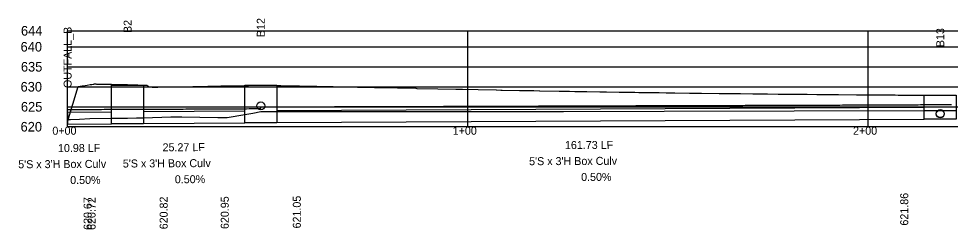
# Model space of a CAD drawing. Extents: x 2253035 to 2279930, y 13774972 to 13793443.
# Drawn here: x 2258373.2 to 2258605.9, y 13793378.5 to 13793431.3 of the extents above; entities that cross this region are included whole.
import ezdxf

# ---------------------------------------------------------------- set-up
doc = ezdxf.new("R2010")
doc.units = 0
for name, color, linetype in [('Default', 7, 'Continuous'), ('E_Utility_ATT_HH', 7, 'Continuous'), ('E_Utility_ATT_PR_PVC', 7, 'Continuous'), ('E_Utility_Electric_Overhead Electric Power Line_OE_Elevation', 7, 'Continuous'), ('E_Utility_Electric_Overhead Electric Power Line_OE_point', 7, 'Continuous'), ('E_Utillity_Water_Water Line_12in', 7, 'Continuous'), ('E_Utillity_Water_Water Line_1in', 7, 'Continuous'), ('E_Utillity_Water_Water Line_4in', 7, 'Continuous'), ('E_Utillity_Water_Water Line_8in', 7, 'Continuous')]:
    doc.layers.add(name, color=color, linetype=linetype)

msp = doc.modelspace()

# ---------------------------------------------------------------- linework, layer by layer
at = {"layer": 'Default'}
for p, q in [((2258485.4, 13793404.21), (2258485.4, 13793428.21)), ((2258585.4, 13793404.21), (2258585.4, 13793428.21))]:
    msp.add_line(p, q, dxfattribs=at)
at = {"layer": 'E_Utility_ATT_PR_PVC'}
for p, q in [((2258400.39, 13793408.64), (2258400.39, 13793408.6)), ((2258433.65, 13793409.25), (2258433.65, 13793409.17)), ((2258603.38, 13793409.85), (2258603.38, 13793409.77))]:
    msp.add_line(p, q, dxfattribs=at)
for points in [[(2258385.4, 13793408.53), (2258386.1, 13793408.54), (2258386.8, 13793408.54), (2258387.51, 13793408.54), (2258388.21, 13793408.54), (2258388.91, 13793408.55), (2258389.62, 13793408.55), (2258390.32, 13793408.55), (2258391.02, 13793408.55), (2258391.72, 13793408.56), (2258392.43, 13793408.56), (2258393.13, 13793408.56), (2258393.83, 13793408.56), (2258394.54, 13793408.57), (2258395.24, 13793408.57), (2258395.94, 13793408.57), (2258396.65, 13793408.57), (2258397.35, 13793408.58), (2258398.05, 13793408.59), (2258398.76, 13793408.59), (2258399.46, 13793408.6), (2258400.16, 13793408.6), (2258400.39, 13793408.61), (2258400.39, 13793408.64)], [(2258400.39, 13793408.6), (2258401.02, 13793408.6), (2258401.65, 13793408.6), (2258402.28, 13793408.6), (2258402.91, 13793408.61), (2258403.55, 13793408.61), (2258404.18, 13793408.61), (2258404.81, 13793408.61), (2258405.44, 13793408.61), (2258406.07, 13793408.62), (2258406.7, 13793408.62), (2258407.34, 13793408.62), (2258407.97, 13793408.62), (2258408.6, 13793408.62), (2258409.23, 13793408.63), (2258409.86, 13793408.63), (2258410.5, 13793408.63), (2258411.13, 13793408.63), (2258411.76, 13793408.64), (2258412.39, 13793408.64), (2258413.02, 13793408.64), (2258413.66, 13793408.64), (2258414.29, 13793408.64), (2258414.92, 13793408.65), (2258415.55, 13793408.65), (2258416.18, 13793408.65), (2258416.82, 13793408.65), (2258417.45, 13793408.66), (2258418.08, 13793408.66), (2258418.71, 13793408.66), (2258419.34, 13793408.66), (2258419.98, 13793408.66), (2258420.61, 13793408.67), (2258421.24, 13793408.67), (2258421.87, 13793408.67), (2258422.5, 13793408.67), (2258423.13, 13793408.67), (2258423.77, 13793408.68), (2258424.4, 13793408.68), (2258425.03, 13793408.68), (2258425.66, 13793408.68), (2258426.29, 13793408.69), (2258426.93, 13793408.69), (2258427.56, 13793408.7), (2258428.19, 13793408.7), (2258428.82, 13793408.71), (2258429.45, 13793408.72), (2258430.09, 13793408.72), (2258430.72, 13793408.73), (2258431.35, 13793408.73), (2258431.98, 13793408.74), (2258432.61, 13793408.74), (2258433.25, 13793408.75), (2258433.65, 13793408.75), (2258433.65, 13793409.25)], [(2258433.65, 13793409.17), (2258434.25, 13793409.17), (2258434.84, 13793409.17), (2258435.43, 13793409.17), (2258436.03, 13793409.17), (2258436.62, 13793409.18), (2258437.21, 13793409.18), (2258437.8, 13793409.18), (2258438.4, 13793409.18), (2258438.99, 13793409.18), (2258439.58, 13793409.18), (2258440.18, 13793409.19), (2258440.77, 13793409.19), (2258441.36, 13793409.19), (2258441.95, 13793409.19), (2258442.55, 13793409.19), (2258443.14, 13793409.2), (2258443.73, 13793409.2), (2258444.33, 13793409.2), (2258444.92, 13793409.2), (2258445.51, 13793409.2), (2258446.1, 13793409.21), (2258446.7, 13793409.21), (2258447.29, 13793409.21), (2258447.88, 13793409.21), (2258448.48, 13793409.21), (2258449.07, 13793409.22), (2258449.66, 13793409.22), (2258450.26, 13793409.22), (2258450.85, 13793409.22), (2258451.44, 13793409.22), (2258452.03, 13793409.23), (2258452.63, 13793409.23), (2258453.22, 13793409.23), (2258453.81, 13793409.23), (2258454.41, 13793409.23), (2258455, 13793409.24), (2258455.59, 13793409.24), (2258456.18, 13793409.24), (2258456.78, 13793409.24), (2258457.37, 13793409.24), (2258457.96, 13793409.25), (2258458.56, 13793409.25), (2258459.15, 13793409.25), (2258459.74, 13793409.25), (2258460.33, 13793409.25), (2258460.93, 13793409.26), (2258461.52, 13793409.26), (2258462.11, 13793409.26), (2258462.71, 13793409.26), (2258463.3, 13793409.26), (2258463.89, 13793409.27), (2258464.49, 13793409.27), (2258465.08, 13793409.27), (2258465.67, 13793409.27), (2258466.26, 13793409.27), (2258466.86, 13793409.28), (2258467.45, 13793409.28), (2258468.04, 13793409.28), (2258468.64, 13793409.28), (2258469.23, 13793409.28), (2258469.82, 13793409.29), (2258470.41, 13793409.29), (2258471.01, 13793409.29), (2258471.6, 13793409.29), (2258472.19, 13793409.29), (2258472.79, 13793409.29), (2258473.38, 13793409.3), (2258473.97, 13793409.3), (2258474.56, 13793409.3), (2258475.16, 13793409.3), (2258475.75, 13793409.3), (2258476.34, 13793409.31), (2258476.94, 13793409.31), (2258477.53, 13793409.31), (2258478.12, 13793409.31), (2258478.72, 13793409.31), (2258479.31, 13793409.32), (2258479.9, 13793409.32), (2258480.49, 13793409.32), (2258481.09, 13793409.32), (2258481.68, 13793409.32), (2258482.27, 13793409.33), (2258482.87, 13793409.33), (2258483.46, 13793409.33), (2258484.05, 13793409.33), (2258484.64, 13793409.33), (2258485.24, 13793409.34), (2258485.83, 13793409.34), (2258486.42, 13793409.34), (2258487.02, 13793409.34), (2258487.61, 13793409.34), (2258488.2, 13793409.35), (2258488.79, 13793409.35), (2258489.39, 13793409.35), (2258489.98, 13793409.35), (2258490.57, 13793409.35), (2258491.17, 13793409.36), (2258491.76, 13793409.36), (2258492.35, 13793409.36), (2258492.95, 13793409.36), (2258493.54, 13793409.36), (2258494.13, 13793409.37), (2258494.72, 13793409.37), (2258495.32, 13793409.37), (2258495.91, 13793409.37), (2258496.5, 13793409.37), (2258497.1, 13793409.38), (2258497.69, 13793409.38), (2258498.28, 13793409.38), (2258498.87, 13793409.38), (2258499.47, 13793409.38), (2258500.06, 13793409.39), (2258500.65, 13793409.39), (2258501.25, 13793409.39), (2258501.84, 13793409.39), (2258502.43, 13793409.39), (2258503.02, 13793409.4), (2258503.62, 13793409.4), (2258504.21, 13793409.4), (2258504.8, 13793409.4), (2258505.4, 13793409.4), (2258505.99, 13793409.4), (2258506.58, 13793409.41), (2258507.18, 13793409.41), (2258507.77, 13793409.41), (2258508.36, 13793409.41), (2258508.95, 13793409.41), (2258509.55, 13793409.42), (2258510.14, 13793409.42), (2258510.73, 13793409.42), (2258511.33, 13793409.42), (2258511.92, 13793409.42), (2258512.51, 13793409.43), (2258513.1, 13793409.43), (2258513.7, 13793409.43), (2258514.29, 13793409.43), (2258514.88, 13793409.43), (2258515.48, 13793409.44), (2258516.07, 13793409.44), (2258516.66, 13793409.44), (2258517.25, 13793409.44), (2258517.85, 13793409.44), (2258518.44, 13793409.45), (2258519.03, 13793409.45), (2258519.63, 13793409.45), (2258520.22, 13793409.45), (2258520.81, 13793409.45), (2258521.41, 13793409.46), (2258522, 13793409.46), (2258522.59, 13793409.46), (2258523.18, 13793409.46), (2258523.78, 13793409.46), (2258524.37, 13793409.47), (2258524.96, 13793409.47), (2258525.56, 13793409.47), (2258526.15, 13793409.47), (2258526.74, 13793409.47), (2258527.33, 13793409.48), (2258527.93, 13793409.48), (2258528.52, 13793409.48), (2258529.11, 13793409.48), (2258529.71, 13793409.48), (2258530.3, 13793409.49), (2258530.89, 13793409.49), (2258531.49, 13793409.49), (2258532.08, 13793409.49), (2258532.67, 13793409.49), (2258533.26, 13793409.5), (2258533.86, 13793409.5), (2258534.45, 13793409.5), (2258535.04, 13793409.5), (2258535.64, 13793409.5), (2258536.23, 13793409.51), (2258536.82, 13793409.51), (2258537.41, 13793409.51), (2258538.01, 13793409.51), (2258538.6, 13793409.51), (2258539.19, 13793409.52), (2258539.79, 13793409.52), (2258540.38, 13793409.52), (2258540.97, 13793409.52), (2258541.56, 13793409.52), (2258542.16, 13793409.52), (2258542.75, 13793409.53), (2258543.34, 13793409.53), (2258543.94, 13793409.53), (2258544.53, 13793409.53), (2258545.12, 13793409.53), (2258545.72, 13793409.54), (2258546.31, 13793409.54), (2258546.9, 13793409.54), (2258547.49, 13793409.54), (2258548.09, 13793409.54), (2258548.68, 13793409.55), (2258549.27, 13793409.55), (2258549.87, 13793409.55), (2258550.46, 13793409.55), (2258551.05, 13793409.55), (2258551.64, 13793409.56), (2258552.24, 13793409.56), (2258552.83, 13793409.56), (2258553.42, 13793409.56), (2258554.02, 13793409.56), (2258554.61, 13793409.57), (2258555.2, 13793409.57), (2258555.79, 13793409.57), (2258556.39, 13793409.57), (2258556.98, 13793409.57), (2258557.57, 13793409.58), (2258558.17, 13793409.58), (2258558.76, 13793409.58), (2258559.35, 13793409.58), (2258559.95, 13793409.58), (2258560.54, 13793409.59), (2258561.13, 13793409.59), (2258561.72, 13793409.59), (2258562.32, 13793409.59), (2258562.91, 13793409.59), (2258563.5, 13793409.6), (2258564.1, 13793409.6), (2258564.69, 13793409.6), (2258565.28, 13793409.6), (2258565.87, 13793409.6), (2258566.47, 13793409.61), (2258567.06, 13793409.61), (2258567.65, 13793409.61), (2258568.25, 13793409.61), (2258568.84, 13793409.61), (2258569.43, 13793409.62), (2258570.02, 13793409.62), (2258570.62, 13793409.62), (2258571.21, 13793409.62), (2258571.8, 13793409.62), (2258572.4, 13793409.63), (2258572.99, 13793409.63), (2258573.58, 13793409.63), (2258574.18, 13793409.63), (2258574.77, 13793409.63), (2258575.36, 13793409.63), (2258575.95, 13793409.64), (2258576.55, 13793409.64), (2258577.14, 13793409.64), (2258577.73, 13793409.64), (2258578.33, 13793409.64), (2258578.92, 13793409.65), (2258579.51, 13793409.65), (2258580.1, 13793409.65), (2258580.7, 13793409.65), (2258581.29, 13793409.65), (2258581.88, 13793409.66), (2258582.48, 13793409.66), (2258583.07, 13793409.66), (2258583.66, 13793409.66), (2258584.25, 13793409.66), (2258584.85, 13793409.67), (2258585.44, 13793409.67), (2258586.03, 13793409.67), (2258586.63, 13793409.67), (2258587.22, 13793409.67), (2258587.81, 13793409.68), (2258588.41, 13793409.68), (2258589, 13793409.68), (2258589.59, 13793409.68), (2258590.18, 13793409.68), (2258590.78, 13793409.69), (2258591.37, 13793409.69), (2258591.96, 13793409.69), (2258592.56, 13793409.69), (2258593.15, 13793409.69), (2258593.74, 13793409.7), (2258594.33, 13793409.7), (2258594.93, 13793409.7), (2258595.52, 13793409.7), (2258596.11, 13793409.71), (2258596.71, 13793409.71), (2258597.3, 13793409.72), (2258597.89, 13793409.72), (2258598.48, 13793409.73), (2258599.08, 13793409.73), (2258599.67, 13793409.74), (2258600.26, 13793409.74), (2258600.86, 13793409.75), (2258601.45, 13793409.75), (2258602.04, 13793409.76), (2258602.64, 13793409.76), (2258603.23, 13793409.77), (2258603.38, 13793409.77), (2258603.38, 13793409.85)], [(2258603.38, 13793409.77), (2258603.94, 13793409.78), (2258604.49, 13793409.78), (2258605.04, 13793409.78), (2258605.6, 13793409.78), (2258606.15, 13793409.78)]]:
    msp.add_lwpolyline(points, dxfattribs=at)
at = {"layer": 'E_Utility_Electric_Overhead Electric Power Line_OE_Elevation'}
for p, q in [((2258385.4, 13793424.21), (2259679.58, 13793424.21)), ((2258385.4, 13793419.21), (2259679.58, 13793419.21)), ((2258385.4, 13793414.21), (2259679.58, 13793414.21)), ((2258385.4, 13793409.21), (2259679.58, 13793409.21))]:
    msp.add_line(p, q, dxfattribs=at)
at = {"layer": 'E_Utility_Electric_Overhead Electric Power Line_OE_point'}
msp.add_lwpolyline([(2258385.4, 13793404.21), (2258385.4, 13793428.21), (2259679.58, 13793428.21), (2259679.58, 13793404.21)], close=True, dxfattribs=at)
at = {"layer": 'E_Utillity_Water_Water Line_12in'}
for points in [[(2258396.39, 13793414.64), (2258404.39, 13793414.64), (2258404.39, 13793404.93), (2258396.39, 13793404.93)], [(2258429.65, 13793414.61), (2258437.65, 13793414.61), (2258437.65, 13793405.16), (2258429.65, 13793405.16)], [(2258599.38, 13793412.09), (2258607.38, 13793412.09), (2258607.38, 13793406.07), (2258599.38, 13793406.07)], [(2258385.4, 13793407.87), (2258385.4, 13793407.87), (2258385.4, 13793404.88), (2258385.4, 13793404.88)]]:
    msp.add_lwpolyline(points, close=True, dxfattribs=at)
at = {"layer": 'E_Utillity_Water_Water Line_1in'}
msp.add_lwpolyline([(2258385.4, 13793406.02), (2258385.4, 13793406.02), (2258385.4, 13793406.02), (2258386.09, 13793406.04), (2258388.33, 13793406.11), (2258390.98, 13793406.26), (2258396.39, 13793406.33), (2258396.39, 13793406.33), (2258400.39, 13793406.38), (2258400.39, 13793406.38), (2258402.6, 13793406.41), (2258404.39, 13793406.47), (2258404.39, 13793406.47), (2258411.21, 13793406.71), (2258413.92, 13793406.7), (2258422.91, 13793406.53), (2258425.29, 13793406.51), (2258429.65, 13793407.24), (2258429.65, 13793407.24), (2258431.69, 13793407.58), (2258433.65, 13793407.99), (2258433.65, 13793407.99), (2258437.65, 13793407.98), (2258437.65, 13793407.98), (2258509.23, 13793407.98), (2258534.41, 13793408.08), (2258599.38, 13793408.26), (2258599.38, 13793408.26), (2258603.38, 13793408.29), (2258603.38, 13793408.29), (2258607.38, 13793408.31)], dxfattribs=at)
at = {"layer": 'E_Utillity_Water_Water Line_4in'}
for p, q in [((2258404.39, 13793408.04), (2258429.65, 13793408.16)), ((2258437.65, 13793408.26), (2258599.38, 13793409.07)), ((2258385.4, 13793407.88), (2258396.39, 13793407.93)), ((2258437.65, 13793405.26), (2258599.38, 13793406.07)), ((2258385.4, 13793404.88), (2258396.39, 13793404.93)), ((2258404.39, 13793405.04), (2258429.65, 13793405.16))]:
    msp.add_line(p, q, dxfattribs=at)
for centre in [(2258433.65, 13793409.41), (2258603.38, 13793407.5), (2258603.38, 13793407.42)]:
    msp.add_circle(centre, 1, dxfattribs=at)
at = {"layer": 'E_Utillity_Water_Water Line_8in'}
msp.add_lwpolyline([(2258385.4, 13793405.41), (2258385.4, 13793405.41), (2258385.4, 13793405.41), (2258388.06, 13793414.25), (2258388.06, 13793414.25), (2258388.09, 13793414.25), (2258388.11, 13793414.26), (2258388.5, 13793414.32), (2258389.05, 13793414.41), (2258389.28, 13793414.45), (2258390.25, 13793414.61), (2258391.05, 13793414.75), (2258391.45, 13793414.81), (2258391.86, 13793414.88), (2258391.92, 13793414.89), (2258391.94, 13793414.89), (2258392, 13793414.9), (2258392.48, 13793414.9), (2258392.58, 13793414.89), (2258395.28, 13793414.84), (2258396.39, 13793414.82), (2258396.39, 13793414.82), (2258396.73, 13793414.81), (2258398.28, 13793414.78), (2258398.48, 13793414.78), (2258398.62, 13793414.77), (2258400.36, 13793414.74), (2258400.39, 13793414.74), (2258400.39, 13793414.74), (2258401.63, 13793414.71), (2258402.95, 13793414.68), (2258404.39, 13793414.64), (2258404.39, 13793414.64), (2258405.19, 13793414.61), (2258405.37, 13793414.47), (2258405.45, 13793414.41), (2258405.6, 13793414.3), (2258405.65, 13793414.26), (2258405.71, 13793414.21), (2258405.86, 13793414.19), (2258406.13, 13793414.16), (2258406.53, 13793414.12), (2258406.67, 13793414.1), (2258406.67, 13793414.1), (2258406.74, 13793414.09), (2258406.79, 13793414.09), (2258406.8, 13793414.09), (2258406.83, 13793414.08), (2258406.9, 13793414.08), (2258407.35, 13793414.08), (2258407.44, 13793414.09), (2258407.74, 13793414.09), (2258407.77, 13793414.09), (2258407.95, 13793414.1), (2258411.34, 13793414.17), (2258411.45, 13793414.17), (2258411.51, 13793414.17), (2258412.16, 13793414.18), (2258413.7, 13793414.21), (2258416.69, 13793414.27), (2258417.74, 13793414.29), (2258420.46, 13793414.35), (2258421.37, 13793414.37), (2258423.65, 13793414.41), (2258425.15, 13793414.44), (2258427.16, 13793414.48), (2258429.65, 13793414.53), (2258429.65, 13793414.53), (2258430.58, 13793414.55), (2258431.49, 13793414.57), (2258432.51, 13793414.59), (2258432.84, 13793414.59), (2258432.91, 13793414.6), (2258433.65, 13793414.61), (2258433.65, 13793414.61), (2258437.65, 13793414.53), (2258437.65, 13793414.53), (2258438.22, 13793414.52), (2258438.65, 13793414.51), (2258441.38, 13793414.45), (2258442.53, 13793414.43), (2258443.3, 13793414.41), (2258447.68, 13793414.32), (2258451.68, 13793414.24), (2258451.7, 13793414.24), (2258453.07, 13793414.21), (2258454.09, 13793414.19), (2258454.38, 13793414.19), (2258454.61, 13793414.18), (2258457.77, 13793414.12), (2258462.02, 13793414.03), (2258462.84, 13793414.01), (2258467.83, 13793413.91), (2258472.34, 13793413.82), (2258472.62, 13793413.81), (2258477.89, 13793413.7), (2258482.39, 13793413.61), (2258482.53, 13793413.61), (2258482.62, 13793413.61), (2258483.67, 13793413.59), (2258484.06, 13793413.58), (2258487.98, 13793413.5), (2258492.48, 13793413.41), (2258492.51, 13793413.41), (2258492.53, 13793413.41), (2258493.63, 13793413.39), (2258493.96, 13793413.38), (2258498.28, 13793413.3), (2258501.85, 13793413.24), (2258501.85, 13793413.24), (2258501.87, 13793413.24), (2258503.28, 13793413.21), (2258503.33, 13793413.21), (2258508.2, 13793413.13), (2258510.69, 13793413.09), (2258510.8, 13793413.08), (2258512.1, 13793413.06), (2258512.67, 13793413.05), (2258515.11, 13793413.01), (2258518.36, 13793412.96), (2258519.11, 13793412.95), (2258519.97, 13793412.94), (2258523.15, 13793412.89), (2258527.11, 13793412.83), (2258528.09, 13793412.81), (2258528.49, 13793412.81), (2258528.58, 13793412.81), (2258533.17, 13793412.74), (2258534.92, 13793412.72), (2258535.19, 13793412.71), (2258537.04, 13793412.69), (2258540.74, 13793412.64), (2258542.33, 13793412.62), (2258542.81, 13793412.61), (2258543.61, 13793412.6), (2258543.76, 13793412.6), (2258548.15, 13793412.55), (2258549.58, 13793412.53), (2258549.94, 13793412.53), (2258550.94, 13793412.51), (2258553.49, 13793412.49), (2258556.55, 13793412.45), (2258556.56, 13793412.45), (2258556.67, 13793412.45), (2258557.99, 13793412.44), (2258560.23, 13793412.41), (2258562.91, 13793412.39), (2258563.31, 13793412.38), (2258567.21, 13793412.34), (2258567.96, 13793412.34), (2258569.52, 13793412.32), (2258569.87, 13793412.32), (2258570.16, 13793412.32), (2258572.53, 13793412.29), (2258574.96, 13793412.27), (2258576.27, 13793412.26), (2258576.75, 13793412.26), (2258577.99, 13793412.25), (2258582.48, 13793412.21), (2258582.64, 13793412.21), (2258583.63, 13793412.21), (2258583.73, 13793412.2), (2258587.53, 13793412.18), (2258588.05, 13793412.17), (2258588.57, 13793412.17), (2258592.11, 13793412.15), (2258592.86, 13793412.14), (2258593.29, 13793412.14), (2258593.67, 13793412.14), (2258594.9, 13793412.13), (2258597.53, 13793412.12), (2258599.18, 13793412.11), (2258599.38, 13793412.11), (2258599.38, 13793412.11), (2258600.3, 13793412.1), (2258602.46, 13793412.09), (2258603.38, 13793412.09), (2258603.38, 13793412.09), (2258603.55, 13793412.09), (2258603.63, 13793412.09), (2258603.69, 13793412.09), (2258606, 13793412.08)], dxfattribs=at)

# ---------------------------------------------------------------- texts
at = {"layer": 'Default'}
for s, height, p in [('644', 2.4, (2258373.75, 13793427.01)), ('640', 2.4, (2258373.65, 13793423.01)), ('635', 2.4, (2258373.73, 13793418.01)), ('630', 2.4, (2258373.65, 13793413.01)), ('625', 2.4, (2258373.73, 13793408.01)), ('620', 2.4, (2258373.65, 13793403.01)), ('0+00', 2, (2258381.59, 13793402.21)), ('1+00', 2, (2258481.59, 13793402.21)), ('2+00', 2, (2258581.59, 13793402.21))]:
    msp.add_text(s, height=height, dxfattribs=at).set_placement(p)
at = {"layer": 'E_Utility_ATT_HH'}
for s, rotation, p in [('OUTFALL_B', 90, (2258386.4, 13793413.9)), ('B2', 90, (2258401.39, 13793427.65)), ('B12', 90, (2258434.65, 13793426.63)), ('B13', 90, (2258604.38, 13793424.11)), ('10.98 LF', 0.2865, (2258383, 13793397.87)), ('25.27 LF', 0.2865, (2258409.12, 13793398.06)), ('161.73 LF', 0.2865, (2258509.63, 13793398.62)), ("5'S x 3'H Box Culv", 0.2865, (2258500.68, 13793394.58)), ("5'S x 3'H Box Culv", 0.2865, (2258373.06, 13793393.82)), ("5'S x 3'H Box Culv", 0.2865, (2258399.19, 13793394.01)), ('0.50%', 0.2865, (2258386.05, 13793389.88)), ('0.50%', 0.2865, (2258412.18, 13793390.07)), ('0.50%', 0.2865, (2258513.67, 13793390.64)), ('621.86', 90, (2258595.38, 13793379.49)), ('620.67', 90, (2258391.4, 13793378.41)), ('620.72', 90, (2258392.39, 13793378.4)), ('620.82', 90, (2258410.39, 13793378.56)), ('620.95', 90, (2258425.65, 13793378.63)), ('621.05', 90, (2258443.65, 13793378.78))]:
    msp.add_text(s, height=2, rotation=rotation, dxfattribs=at).set_placement(p)

doc.saveas('drawing.dxf')
